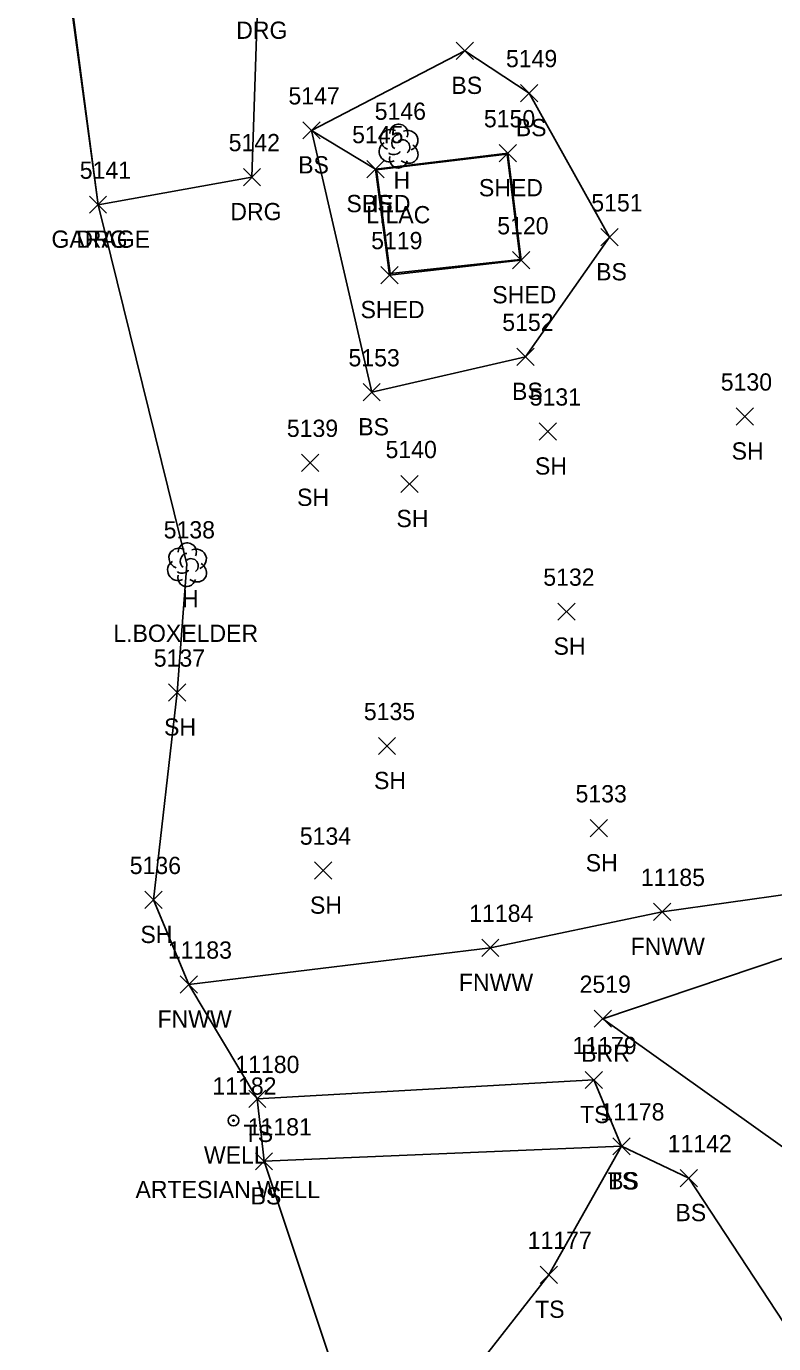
# Model space of a CAD drawing. Extents: x 1439173 to 1457902, y 641926 to 659889.
# Drawn here: x 1447777.6 to 1447864.3, y 648320.9 to 648473.7 of the extents above; entities that cross this region are included whole.
import ezdxf

# ---------------------------------------------------------------- set-up
doc = ezdxf.new("R2010")
doc.units = 0
for name, color, linetype in [('L_A', 7, 'Continuous'), ('L_C', 7, 'Continuous'), ('L_I', 7, 'Continuous'), ('L_TIC', 7, 'Continuous'), ('LABL', 7, 'Continuous'), ('LBC', 7, 'Continuous'), ('LELB', 7, 'Continuous'), ('Level 5', 7, 'Continuous'), ('LFNC', 7, 'Continuous'), ('LSOGP', 7, 'Continuous'), ('LTD', 7, 'Continuous'), ('R_A', 7, 'Continuous'), ('R_I', 7, 'Continuous'), ('R_TIC', 7, 'Continuous'), ('RDG', 7, 'Continuous'), ('U_A', 7, 'Continuous'), ('U_C', 7, 'Continuous'), ('U_I', 7, 'Continuous'), ('UWW', 7, 'Continuous')]:
    doc.layers.add(name, color=color, linetype=linetype)

msp = doc.modelspace()

# ---------------------------------------------------------------- linework, layer by layer
at = {"layer": 'L_TIC'}
for points in [[(1447827.44, 648469.83), (1447829.44, 648471.83)], [(1447829.44, 648469.83), (1447827.44, 648471.83)], [(1447834.91, 648464.93), (1447836.91, 648466.93)], [(1447836.91, 648464.93), (1447834.91, 648466.93)], [(1447809.66, 648460.61), (1447811.66, 648462.61)], [(1447811.66, 648460.61), (1447809.66, 648462.61)], [(1447809.66, 648460.61), (1447811.66, 648462.61)], [(1447811.66, 648460.61), (1447809.66, 648462.61)], [(1447832.43, 648457.96), (1447834.43, 648459.96)], [(1447834.43, 648457.96), (1447832.43, 648459.96)], [(1447832.43, 648457.96), (1447834.43, 648459.96)], [(1447834.43, 648457.96), (1447832.43, 648459.96)], [(1447817.06, 648456.12), (1447819.06, 648458.12)], [(1447819.06, 648456.12), (1447817.06, 648458.12)], [(1447817.06, 648456.12), (1447819.06, 648458.12)], [(1447819.06, 648456.12), (1447817.06, 648458.12)], [(1447784.88, 648451.99), (1447786.88, 648453.99)], [(1447786.88, 648451.99), (1447784.88, 648453.99)], [(1447844.23, 648448.21), (1447846.23, 648450.21)], [(1447846.23, 648448.21), (1447844.23, 648450.21)], [(1447833.98, 648445.55), (1447835.98, 648447.55)], [(1447835.98, 648445.55), (1447833.98, 648447.55)], [(1447818.71, 648443.83), (1447820.71, 648445.83)], [(1447820.71, 648443.83), (1447818.71, 648445.83)], [(1447818.71, 648443.83), (1447820.71, 648445.83)], [(1447820.71, 648443.83), (1447818.71, 648445.83)], [(1447834.47, 648434.35), (1447836.47, 648436.35)], [(1447836.47, 648434.35), (1447834.47, 648436.35)], [(1447816.63, 648430.24), (1447818.63, 648432.24)], [(1447818.63, 648430.24), (1447816.63, 648432.24)], [(1447816.63, 648430.24), (1447818.63, 648432.24)], [(1447818.63, 648430.24), (1447816.63, 648432.24)], [(1447859.91, 648427.43), (1447861.91, 648429.43)], [(1447861.91, 648427.43), (1447859.91, 648429.43)], [(1447837.08, 648425.69), (1447839.08, 648427.69)], [(1447839.08, 648425.69), (1447837.08, 648427.69)], [(1447809.49, 648422.06), (1447811.49, 648424.06)], [(1447811.49, 648422.06), (1447809.49, 648424.06)], [(1447821.02, 648419.6), (1447823.02, 648421.6)], [(1447823.02, 648419.6), (1447821.02, 648421.6)], [(1447839.24, 648404.8), (1447841.24, 648406.8)], [(1447841.24, 648404.8), (1447839.24, 648406.8)], [(1447794.05, 648395.42), (1447796.05, 648397.42)], [(1447796.05, 648395.42), (1447794.05, 648397.42)], [(1447818.41, 648389.22), (1447820.41, 648391.22)], [(1447820.41, 648389.22), (1447818.41, 648391.22)], [(1447842.97, 648379.68), (1447844.97, 648381.68)], [(1447844.97, 648379.68), (1447842.97, 648381.68)], [(1447810.99, 648374.77), (1447812.99, 648376.77)], [(1447812.99, 648374.77), (1447810.99, 648376.77)], [(1447791.31, 648371.37), (1447793.31, 648373.37)], [(1447793.31, 648371.37), (1447791.31, 648373.37)], [(1447850.32, 648369.99), (1447852.32, 648371.99)], [(1447852.32, 648369.99), (1447850.32, 648371.99)], [(1447830.4, 648365.82), (1447832.4, 648367.82)], [(1447832.4, 648365.82), (1447830.4, 648367.82)], [(1447795.43, 648361.56), (1447797.43, 648363.56)], [(1447797.43, 648361.56), (1447795.43, 648363.56)], [(1447843.46, 648357.6), (1447845.46, 648359.6)], [(1447845.46, 648357.6), (1447843.46, 648359.6)], [(1447842.4, 648350.49), (1447844.4, 648352.49)], [(1447844.4, 648350.49), (1447842.4, 648352.49)], [(1447803.36, 648348.3), (1447805.36, 648350.3)], [(1447805.36, 648348.3), (1447803.36, 648350.3)], [(1447845.62, 648342.8), (1447847.62, 648344.8)], [(1447847.62, 648342.8), (1447845.62, 648344.8)], [(1447845.62, 648342.8), (1447847.62, 648344.8)], [(1447847.62, 648342.8), (1447845.62, 648344.8)], [(1447804.14, 648341.06), (1447806.14, 648343.06)], [(1447806.14, 648341.06), (1447804.14, 648343.06)], [(1447853.43, 648339.12), (1447855.43, 648341.12)], [(1447855.43, 648339.12), (1447853.43, 648341.12)], [(1447837.18, 648327.91), (1447839.18, 648329.91)], [(1447839.18, 648327.91), (1447837.18, 648329.91)]]:
    msp.add_lwpolyline(points, dxfattribs=at)
at = {"layer": 'LABL'}
msp.add_lwpolyline([(1447975.52, 648148.69), (1447981.52, 648110.97), (1447974.2, 648092.22), (1447958.64, 648075.67), (1447941.87, 648100.07), (1447936.57, 648139.24), (1447926.83, 648188.41), (1447923.24, 648233.98), (1447912.22, 648276.03), (1447890.52, 648312.32), (1447885.31, 648329.49), (1447844.46, 648358.6), (1447883.24, 648371.65), (1447915.86, 648376.25), (1447938.91, 648380.03), (1447948.39, 648332.97), (1447948.3, 648332.92), (1447954.84, 648284.4)], dxfattribs=at)
at = {"layer": 'LBC'}
for points in [[(1447785.88, 648452.99), (1447781.78, 648484.45), (1447781.25, 648487.93), (1447780.78, 648490.7)], [(1447819.71, 648444.83), (1447818.06, 648457.12), (1447833.43, 648458.96)], [(1447819.71, 648444.83), (1447834.98, 648446.55), (1447833.43, 648458.96)]]:
    msp.add_lwpolyline(points, dxfattribs=at)
at = {"layer": 'LELB'}
for points in [[(1447818.06, 648457.12), (1447810.66, 648461.61), (1447828.44, 648470.83), (1447835.91, 648465.93), (1447845.23, 648449.21), (1447835.47, 648435.35), (1447817.63, 648431.24)], [(1447810.66, 648461.61), (1447817.63, 648431.24)], [(1447948.66, 648059.36), (1447926.41, 648053.33), (1447891.46, 648047.11), (1447863.43, 648042.99), (1447838.8, 648055.7), (1447830.08, 648068.33), (1447823.25, 648098.35), (1447824.6, 648130.92), (1447826.26, 648169.98), (1447850.4, 648199.29), (1447852.29, 648220.54), (1447848.64, 648251.48), (1447842.22, 648253.37), (1447832.83, 648267.7), (1447823.82, 648274.65), (1447821.27, 648293.75), (1447827.09, 648314.7), (1447838.18, 648328.91), (1447846.62, 648343.8), (1447843.4, 648351.49), (1447804.36, 648349.3)], [(1447925.77, 648058.24), (1447929.14, 648088.66), (1447919.16, 648115.38), (1447915.7, 648147.78), (1447907.31, 648180.91), (1447901.37, 648223.58), (1447896.17, 648258.23), (1447883.2, 648295.32), (1447866.25, 648322.11), (1447854.43, 648340.12), (1447846.62, 648343.8), (1447805.14, 648342.06)]]:
    msp.add_lwpolyline(points, dxfattribs=at)
at = {"layer": 'Level 5'}
msp.add_lwpolyline([(1447818.17, 648457.03), (1447833.34, 648458.84), (1447834.87, 648446.64), (1447819.76, 648445)], close=True, dxfattribs=at)
at = {"layer": 'LFNC'}
msp.add_lwpolyline([(1447796.43, 648362.56), (1447831.4, 648366.82), (1447851.32, 648370.99), (1447889.8, 648376.39), (1447924.06, 648380.5)], dxfattribs=at)
at = {"layer": 'LSOGP'}
msp.add_lwpolyline([(1447821.27, 648293.77), (1447805.14, 648342.09), (1447804.36, 648349.32), (1447796.43, 648362.58), (1447792.31, 648372.38), (1447795.05, 648396.42), (1447796.19, 648411.29), (1447785.88, 648452.99), (1447780.78, 648490.7), (1447777.56, 648514.38), (1447782.67, 648520.33), (1447781.51, 648533.74), (1447778.72, 648568.12), (1447787.13, 648603.86), (1447785.52, 648634.52), (1447806.44, 648704.32), (1447807.31, 648714.22), (1447804.59, 648719), (1447802.51, 648730.75), (1447800.97, 648741.32), (1447799.79, 648750.94)], dxfattribs=at)
at = {"layer": 'LTD'}
for p, q in [((1447820.73, 648459.83), (1447820.73, 648459.83)), ((1447820.73, 648459.83), (1447820.73, 648459.83)), ((1447796.19, 648411.29), (1447796.19, 648411.29)), ((1447796.19, 648411.29), (1447796.19, 648411.29))]:
    msp.add_line(p, q, dxfattribs=at)
for centre in [(1447820.77, 648461.27), (1447796.24, 648412.72)]:
    msp.add_arc(centre, 1.05, 335.5272, 180.9563, dxfattribs=at)
for centre, major_axis, ratio, start_param, end_param in [((1447819.93, 648460.5), (1.21, -0.51), 0.895232, 1.570796, 4.712389), ((1447821.77, 648460.42), (-1.14, -0.48), 0.949671, 1.570796, 4.712389), ((1447819.64, 648459.13), (0.58, -1.04), 0.959034, 3.141593, 6.283185), ((1447820.52, 648460.29), (-0.208, -0.792), 0.645439, 3.141593, 6.283185), ((1447821.23, 648459.67), (-0.5, 0.667), 0.989748, 3.141593, 6.283185), ((1447820.73, 648458.33), (0.26, 1.06), 0.942809, 1.570796, 4.712389), ((1447820.27, 648459.08), (-0.625, -0.083), 0.423636, 0, 3.141593), ((1447821.73, 648459), (-1.09, 0.79), 0.841452, 1.570796, 4.712389), ((1447795.4, 648411.96), (1.21, -0.51), 0.895232, 1.570796, 4.712389), ((1447795.98, 648411.75), (-0.208, -0.792), 0.645439, 3.141593, 6.283185), ((1447797.23, 648411.87), (-1.14, -0.48), 0.949671, 1.570796, 4.712389), ((1447795.11, 648410.58), (0.58, -1.04), 0.959034, 3.141593, 6.283185), ((1447796.69, 648411.12), (-0.5, 0.667), 0.989748, 3.141593, 6.283185), ((1447797.19, 648410.46), (-1.09, 0.79), 0.841452, 1.570796, 4.712389), ((1447796.19, 648409.79), (0.26, 1.06), 0.942809, 1.570796, 4.712389), ((1447795.73, 648410.54), (-0.625, -0.083), 0.423636, 0, 3.141593)]:
    msp.add_ellipse(centre, major_axis=major_axis, ratio=ratio, start_param=start_param, end_param=end_param, dxfattribs=at)
at = {"layer": 'R_TIC'}
for points in [[(1447802.74, 648455.19), (1447804.74, 648457.19)], [(1447804.74, 648455.19), (1447802.74, 648457.19)], [(1447784.88, 648451.99), (1447786.88, 648453.99)], [(1447786.88, 648451.99), (1447784.88, 648453.99)]]:
    msp.add_lwpolyline(points, dxfattribs=at)
at = {"layer": 'RDG'}
msp.add_lwpolyline([(1447785.88, 648452.99), (1447803.74, 648456.19), (1447804.42, 648477.22), (1447820.83, 648498.8), (1447848.93, 648504.76), (1447875.02, 648509.98), (1447899.52, 648511.7), (1447920.25, 648511.67), (1447931.97, 648504.86), (1447936.25, 648502.67)], dxfattribs=at)
at = {"layer": 'UWW'}
for radius in [0.625, 0.0833]:
    msp.add_circle((1447801.6, 648346.79), radius, dxfattribs=at)

# ---------------------------------------------------------------- texts
at = {"layer": 'L_A'}
for s, p in [('BS', (1447826.88, 648465.83)), ('BS', (1447834.35, 648460.93)), ('BS', (1447809.1, 648456.61)), ('BS', (1447809.1, 648456.61)), ('H', (1447820.16, 648454.83)), ('SHED', (1447830.07, 648453.96)), ('SHED', (1447830.07, 648453.96)), ('SHED', (1447814.7, 648452.12)), ('BS', (1447816.5, 648452.12)), ('GARAGE', (1447780.48, 648447.99)), ('BS', (1447843.67, 648444.21)), ('SHED', (1447831.62, 648441.55)), ('SHED', (1447816.34, 648439.83)), ('SHED', (1447816.34, 648439.83)), ('BS', (1447833.91, 648430.35)), ('BS', (1447816.07, 648426.24)), ('BS', (1447816.07, 648426.24)), ('SH', (1447859.39, 648423.43)), ('SH', (1447836.57, 648421.69)), ('SH', (1447808.97, 648418.06)), ('SH', (1447820.5, 648415.6)), ('H', (1447795.62, 648406.29)), ('SH', (1447838.73, 648400.8)), ('SH', (1447793.54, 648391.42)), ('SH', (1447817.9, 648385.22)), ('SH', (1447842.46, 648375.68)), ('SH', (1447810.47, 648370.77)), ('SH', (1447790.8, 648367.37)), ('FNWW', (1447847.67, 648365.99)), ('FNWW', (1447827.75, 648361.82)), ('FNWW', (1447792.78, 648357.56)), ('BRR', (1447841.94, 648353.6)), ('TS', (1447841.8, 648346.49)), ('TS', (1447802.77, 648344.3)), ('TS', (1447845.03, 648338.8)), ('BS', (1447845.06, 648338.8)), ('BS', (1447803.58, 648337.06)), ('BS', (1447852.87, 648335.12)), ('TS', (1447836.59, 648323.91))]:
    msp.add_text(s, height=2, dxfattribs=at).set_placement(p)
at = {"layer": 'L_C'}
for s, p in [('LILAC', (1447817, 648450.83)), ('L.BOXELDER', (1447787.66, 648402.29))]:
    msp.add_text(s, height=2, dxfattribs=at).set_placement(p)
at = {"layer": 'L_I'}
for s, p in [('5149', (1447833.21, 648468.93)), ('5147', (1447807.97, 648464.61)), ('5147', (1447807.97, 648464.61)), ('5146', (1447817.98, 648462.83)), ('5150', (1447830.65, 648461.96)), ('5150', (1447830.65, 648461.96)), ('5145', (1447815.36, 648460.12)), ('5145', (1447815.36, 648460.12)), ('5141', (1447783.76, 648455.99)), ('5151', (1447843.11, 648452.21)), ('5120', (1447832.2, 648449.55)), ('5119', (1447817.57, 648447.83)), ('5119', (1447817.57, 648447.83)), ('5152', (1447832.78, 648438.35)), ('5153', (1447814.94, 648434.24)), ('5153', (1447814.94, 648434.24)), ('5130', (1447858.13, 648431.43)), ('5131', (1447835.96, 648429.69)), ('5139', (1447807.79, 648426.06)), ('5140', (1447819.24, 648423.6)), ('5138', (1447793.5, 648414.29)), ('5132', (1447837.54, 648408.8)), ('5137', (1447792.35, 648399.42)), ('5135', (1447816.72, 648393.22)), ('5133', (1447841.28, 648383.68)), ('5134', (1447809.29, 648378.77)), ('5136', (1447789.56, 648375.37)), ('11185', (1447848.86, 648373.99)), ('11184', (1447828.95, 648369.82)), ('11183', (1447793.98, 648365.56)), ('2519', (1447841.75, 648361.6)), ('11179', (1447840.93, 648354.49)), ('11180', (1447801.81, 648352.3)), ('11178', (1447844.16, 648346.8)), ('11178', (1447844.16, 648346.8)), ('11181', (1447803.25, 648345.06)), ('11142', (1447851.97, 648343.12)), ('11177', (1447835.73, 648331.91))]:
    msp.add_text(s, height=2, dxfattribs=at).set_placement(p)
at = {"layer": 'R_A'}
for p in [(1447801.91, 648472.22), (1447801.23, 648451.19), (1447783.37, 648447.99)]:
    msp.add_text('DRG', height=2, dxfattribs=at).set_placement(p)
at = {"layer": 'R_I'}
for s, p in [('5142', (1447801.04, 648459.19)), ('5141', (1447783.76, 648455.99))]:
    msp.add_text(s, height=2, dxfattribs=at).set_placement(p)
at = {"layer": 'U_A'}
msp.add_text('WELL', height=2, dxfattribs=at).set_placement((1447798.17, 648341.79))
at = {"layer": 'U_C'}
msp.add_text('ARTESIAN WELL', height=2, dxfattribs=at).set_placement((1447790.23, 648337.79))
at = {"layer": 'U_I'}
msp.add_text('11182', height=2, dxfattribs=at).set_placement((1447799.15, 648349.79))

doc.saveas('drawing.dxf')
